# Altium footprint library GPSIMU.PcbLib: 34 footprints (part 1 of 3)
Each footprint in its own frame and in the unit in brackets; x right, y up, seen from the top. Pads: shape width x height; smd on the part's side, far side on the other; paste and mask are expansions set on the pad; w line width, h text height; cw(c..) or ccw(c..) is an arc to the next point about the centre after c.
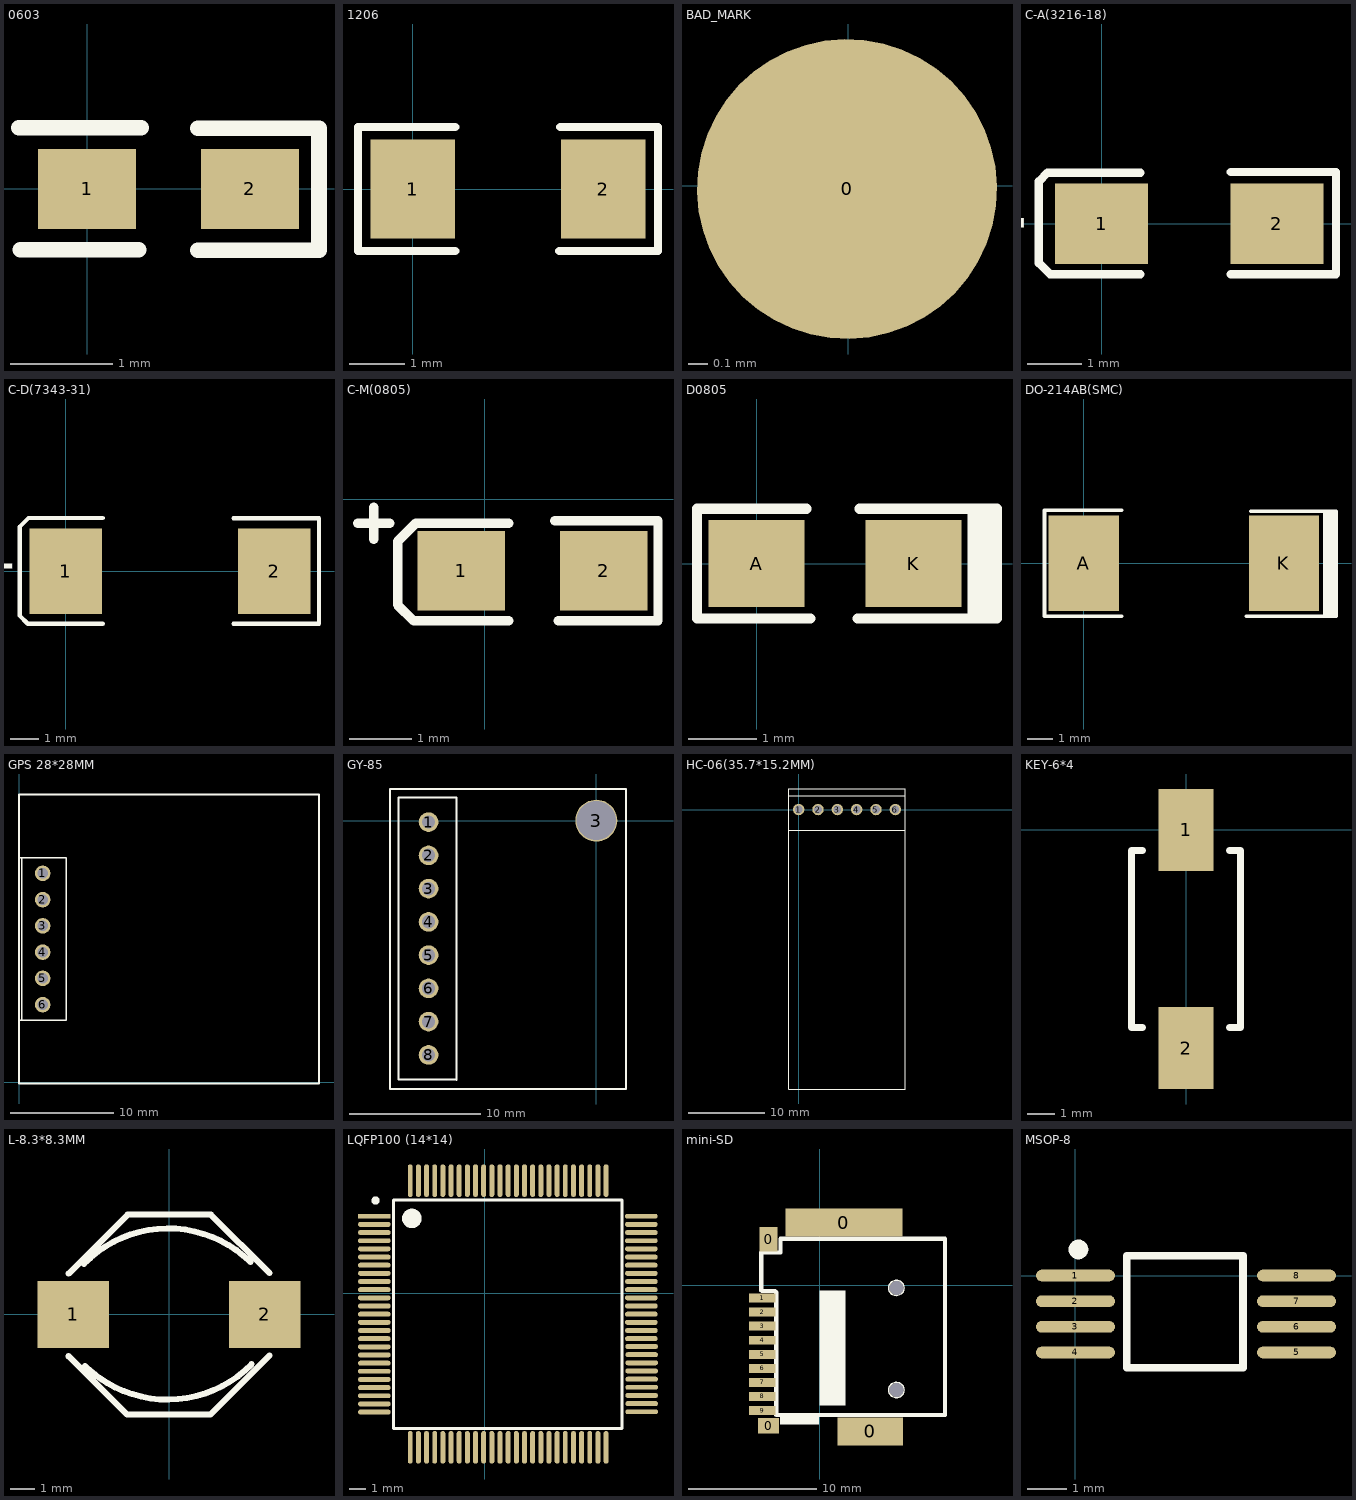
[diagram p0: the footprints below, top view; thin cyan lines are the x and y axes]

## 0603 [mil]
height 39.37
pads (2):
  rect 38x31 smd: 1(0,0) 2(63,0)
Top Overlay:
  lines w6: -26.32,23.62 20.98,23.62 ; -25.82,-23.62 20.08,-23.62 ; 42.9,-23.74 89.7,-23.74 89.7,23.5 42.9,23.5

## 1206 [mil]
height 39.37
pads (2):
  rect 60x70 smd: 1(0,0) 2(135,0)
Top Overlay:
  lines w5.91: 30,-44 -39,-44 -39,44 30,44 ; 104,-44 174,-44 174,44 104.7,44

## BAD_MARK [mil] "MARK 点"
height 39.37
pads (1):
  round 60 smd mask+29.53: 0(-0.25,-0.63)

## C-A(3216-18) [mm]
height 1.6
pads (2):
  rect 1.7x1.47 smd: 1(0,0) 2(3.2,0)
Top Overlay:
  lines w0.152: 0.711,-0.921 -0.94,-0.921 -1.142,-0.719 -1.142,0.773 -0.985,0.93 0.711,0.93 ; 2.356,-0.921 4.276,-0.921 4.276,0.943 2.356,0.943
  text "+" at -1.195,0.662 h1.52

## C-D(7343-31) [mm]
height 2.896
pads (2):
  rect 2.54x3 smd: 1(0,0) 2(7.3,0)
Top Overlay:
  lines w0.152: 1.295,-1.845 -1.331,-1.845 -1.62,-1.556 -1.62,1.55 -1.31,1.86 1.295,1.859 ; 5.876,-1.845 8.869,-1.845 8.869,1.849 5.876,1.849
  text "+" at -1.641,0.821 h1.52

## C-M(0805) [mil] "钽电容"
pads (2):
  rect 55.12x50 smd: 1(-15,-45) 2(75,-45)
Top Overlay:
  lines w5.91: 44.13,-13.5 109.13,-13.5 109.13,-76.5 46.35,-76.5
  lines w6: -80,-15 -60,-15 ; -70,-25 -70,-5 ; 15,-76.5 -45,-76.5 -55,-66.5 -55,-26.5 -43.5,-15 15,-15

## D0805 [mm]
height 1
pads (2):
  rect 1.4x1.27 smd: A(0,0) K(2.286,0)
Top Overlay:
  rectangle: 3.074,-0.811 3.464,0.789
  lines w0.15: 0.728,0.8 -0.867,0.8 -0.867,-0.8 0.784,-0.8 ; 1.473,-0.8 3.501,-0.8 3.501,0.8 1.499,0.8

## DO-214AB(SMC) [mm] "SMC CASE 403 PLASTIC SMCJ-1500W"
height 1
pads (2):
  rect 2.79x3.8 smd: A(0,0) K(7.95,0)
Top Overlay:
  rectangle: 9.491,-2.166 9.966,2.056
  lines w0.15: 1.5,-2.111 -1.567,-2.111 -1.567,2.095 1.5,2.095 ; 6.456,-2.111 10.016,-2.111 10.016,2.056 6.632,2.056

## GPS 28*28MM [mm] "28*28MM  BS-280"
pads (6):
  round 1.5 hole 1.016: 1(2.296,20.193) 2(2.296,17.653) 3(2.296,15.113) 4(2.296,12.573) 5(2.296,10.033) 6(2.296,7.493)
Top Overlay:
  lines w0.152: 0,5.969 4.582,5.969 4.582,21.717 0,21.717 ; 0.264,5.969 0.264,21.717 ; 0,-0.127 29.01,-0.127 29.01,27.813 0,27.813 0,-0.127

## GY-85 [mm] "22*17MM"
pads (9):
  round 1.5 hole 1.016: 1(-12.817,-0.114) 2(-12.817,-2.654) 3(-12.817,-5.194) 4(-12.817,-7.734) 5(-12.817,-10.274) 6(-12.817,-12.814) 7(-12.817,-15.354) 8(-12.817,-17.894)
  round 3.2 hole 3: 3(0,0)
Top Overlay:
  lines w0.152: -15.748,-20.498 -15.748,2.413 2.252,2.413 2.252,-20.498 -15.725,-20.498 ; -15.116,-19.787 -15.113,-19.784 -15.113,-17.272 ; -15.116,-12.167 -15.113,-12.164 -15.113,-9.652 -15.113,1.778 -10.668,1.778 -10.668,-19.812 ; -15.11,-19.787 -10.668,-19.787 ; -15.116,-17.247 -15.113,-17.244 ; -15.116,-17.247 -15.113,-17.244 ; -15.116,-17.247 -15.113,-17.244 ; -15.116,-14.707 -15.113,-14.704 ; -15.116,-14.707 -15.113,-14.704 ; -15.116,-14.707 -15.113,-14.704 ; -15.113,-17.244 -15.113,-14.732 ; -15.113,-17.244 -15.113,-14.732 ; -15.113,-17.244 -15.113,-14.732 ; -15.113,-14.704 -15.113,-12.192 -15.113,-14.704

## HC-06(35.7*15.2MM) [mm] "蓝牙模块"
height 1
pads (6):
  round 1.5 hole 1.016: 1(0,0) 2(2.54,0) 3(5.08,0) 4(7.62,0) 5(10.16,0) 6(12.7,0)
Top Overlay:
  lines w0.152: -1.321,1.8 14.03,1.8 ; -1.33,-2.7 -1.33,-36.719 14.03,-36.719 14.03,-2.7 ; -1.33,-2.7 14.03,-2.7 ; -1.33,-2.7 -1.33,2.7 14.03,2.7 14.03,-2.7

## KEY-6*4 [mm] "2PIN"
height 1
pads (2):
  rect 2x3 smd: 1(0,0) 2(0,-8)
Top Overlay:
  lines w0.254: -1.6,-7.25 -2,-7.25 -2,-0.75 -1.6,-0.75 ; 1.6,-7.25 2,-7.25 2,-0.75 1.6,-0.75

## L-8.3*8.3MM [mm] "68uH 1.5A"
height 4.5
pads (2):
  rect 3x2.8 smd: 1(-4,0) 2(4,0)
Top Overlay:
  lines w0.254: -4.191,-1.753 -1.753,-4.191 1.727,-4.191 4.191,-1.727 ; -4.191,1.702 -1.727,4.166 1.753,4.166 4.191,1.727 ; -3.556,2.108 cw(c-0.038,-1.333) 3.404,2.184 ; -3.505,-2.159 ccw(c-0.064,1.359) 3.454,-2.083

## LQFP100 (14*14) [mm]
height 1
pads (100):
  rect 2x0.3 smd: 1(-6.751,4.716)
  oval 2x0.3 smd: 2(-6.751,4.216) 3(-6.751,3.716) 4(-6.751,3.216) 5(-6.751,2.716) 6(-6.751,2.216) 7(-6.751,1.716) 8(-6.751,1.216) 9(-6.751,0.716) 10(-6.751,0.216) 11(-6.751,-0.284) 12(-6.751,-0.784) 13(-6.751,-1.284) 14(-6.751,-1.784) 15(-6.751,-2.284) 16(-6.751,-2.784) 17(-6.751,-3.284) 18(-6.751,-3.784) 19(-6.751,-4.284) 20(-6.751,-4.784) 21(-6.751,-5.284) 22(-6.751,-5.784) 23(-6.751,-6.284) 24(-6.751,-6.784) 25(-6.751,-7.284) 51(9.629,-7.264) 52(9.629,-6.764) 53(9.629,-6.264) 54(9.629,-5.764) 55(9.629,-5.264) 56(9.629,-4.764) 57(9.629,-4.264) 58(9.629,-3.764) 59(9.629,-3.264) 60(9.609,-2.784) 61(9.609,-2.284) 62(9.609,-1.784) 63(9.609,-1.284) 64(9.609,-0.784) 65(9.609,-0.284) 66(9.609,0.216) 67(9.609,0.716) 68(9.609,1.216) 69(9.609,1.716) 70(9.609,2.216) 71(9.609,2.716) 72(9.609,3.216) 73(9.609,3.716) 74(9.609,4.216) 75(9.609,4.716)
  oval 0.3x2 smd: 26(-4.551,-9.444) 27(-4.051,-9.444) 28(-3.551,-9.444) 29(-3.051,-9.444) 30(-2.551,-9.444) 31(-2.051,-9.444) 32(-1.551,-9.444) 33(-1.051,-9.444) 34(-0.551,-9.444) 35(-0.051,-9.444) 36(0.449,-9.444) 37(0.949,-9.444) 38(1.449,-9.444) 39(1.949,-9.444) 40(2.449,-9.444) 41(2.949,-9.444) 42(3.449,-9.444) 43(3.949,-9.444) 44(4.449,-9.444) 45(4.949,-9.444) 46(5.449,-9.444) 47(5.949,-9.444) 48(6.449,-9.444) 49(6.949,-9.444) 50(7.449,-9.444) 76(7.449,6.896) 77(6.949,6.896) 78(6.449,6.896) 79(5.949,6.896) 80(5.449,6.896) 81(4.949,6.896) 82(4.449,6.896) 83(3.949,6.896) 84(3.449,6.896) 85(2.949,6.896) 86(2.449,6.896) 87(1.949,6.896) 88(1.449,6.896) 89(0.949,6.896) 90(0.449,6.896) 91(-0.051,6.896) 92(-0.551,6.896) 93(-1.051,6.896) 94(-1.551,6.896) 95(-2.051,6.896) 96(-2.551,6.896) 97(-3.051,6.896) 98(-3.551,6.896) 99(-4.051,6.896) 100(-4.551,6.896)
Top Overlay:
  circle w0.25: c-6.676,5.676 r0.125
  circle w0.6: c-4.451,4.581 r0.3
  lines w0.2: -5.571,-7.664 -5.571,5.716 -4.871,5.716 ; -5.571,-7.524 -5.571,-8.284 7.809,-8.284 ; -4.951,5.716 7.829,5.716 ; 7.729,-8.284 8.429,-8.284 8.429,5.716 7.809,5.716

## mini-SD [mm]
height 1
pads (15):
  rect 1.629x1.225 smd: 0(-3.99,-11.001)
  rect 1.4x1.93 smd: 0(-3.99,3.599)
  rect 9.16x2.2 smd: 0(1.911,4.917)
  rect 5.096x2.2 smd: 0(3.969,-11.44)
  rect 2.057x0.7 smd: 1(-4.49,-1.001) 2(-4.49,-2.101) 3(-4.49,-3.201) 4(-4.49,-4.301) 5(-4.49,-5.401) 6(-4.49,-6.501) 7(-4.49,-7.601) 8(-4.49,-8.701) 9(-4.49,-9.801)
  round 1.1 hole 1.1: ""(6.01,-8.201) ""(6.01,-0.201)
Top Overlay:
  circle w0.1: c6.01,-0.201 r0.6
  circle w0.1: c6.01,-8.201 r0.6
  region: -0.04,-10.901 -0.04,-10.201 -3.09,-10.201 -3.09,-10.901
  region: 2.01,-9.401 2.01,-0.401 0.01,-0.401 0.01,-9.401
  lines w0.33: -3.065,3.574 -3.065,2.574 -4.565,2.574 -4.565,-0.401 -4.515,-0.451 -3.49,-0.451 -3.39,-0.551 -3.39,-10.151 9.81,-10.151 9.81,3.649 -3.065,3.649

## MSOP-8 [mm]
height 1
pads (8):
  oval 2x0.3 smd: 1(0,0) 2(0,-0.65) 3(0,-1.3) 4(0,-1.95) 5(5.6,-1.95) 6(5.6,-1.3) 7(5.6,-0.65) 8(5.6,0)
Top Overlay:
  circle w0.25: c0.075,0.66 r0.125
  lines w0.2: 1.3,-2.337 4.242,-2.337 4.242,0.5 1.3,0.5 1.3,-2.337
